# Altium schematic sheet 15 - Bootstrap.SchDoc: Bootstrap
size A3; PageSetup: Record=PageOptions¦CenterHorizontal=True¦CenterVertical=True¦PrintScale=0.70¦XCorrection=1.00¦YCorrection=1.00¦PrintKind=0¦BorderSize=5000000¦LeftOffset=0¦BottomOffset=0¦Orientation=2¦PaperLength=4200¦PaperWidth=2970¦Scale=100¦PaperSource=7¦PrintQuality=600¦MediaType=1¦DitherType=10¦PaperKind=A4¦PrintScaleMode=1; Author: Juan Anzola; SheetNumber: 15; SheetTotal: 20
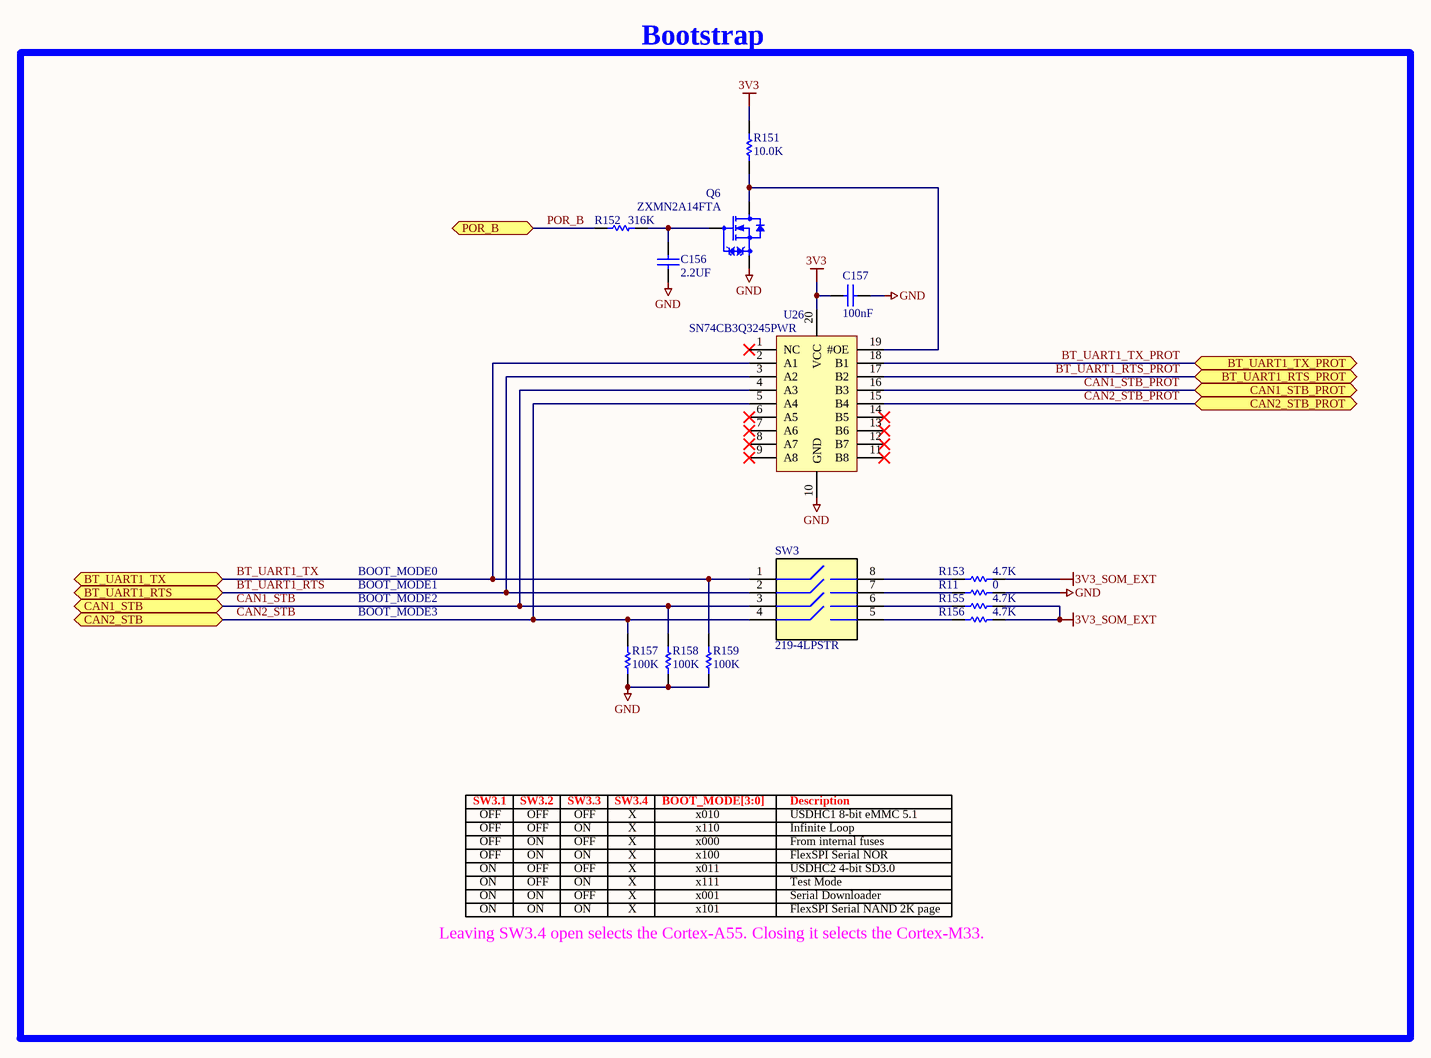
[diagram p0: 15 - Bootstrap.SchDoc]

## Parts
C156  2.2UF  [CAPC1608X90N]
C157  100nF  [CAPC1005X55N]
Q6  ZXMN2A14FTA  [SOT95P240X110_GSD-3N]
R11  0  [RESC1005X40N]
R151  10.0K  [RESC1005X40N]
R152  316K  [RESC1609X55N]
R153  4.7K  [RESC1005X40N]
R155  4.7K  [RESC1005X40N]
R156  4.7K  [RESC1005X40N]
R157  100K  [RESC1005X40N]
R158  100K  [RESC1005X40N]
R159  100K  [RESC1005X40N]
SW3  219-4LPSTR  [SOIC254P991X420-8N]
U26  SN74CB3Q3245PWR  [SOP65P640X120-20N]

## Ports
BT_UART1_RTS (bidir), BT_UART1_RTS_PROT (bidir), BT_UART1_TX (bidir), BT_UART1_TX_PROT (bidir), CAN1_STB (bidir), CAN1_STB_PROT (bidir), CAN2_STB (bidir), CAN2_STB_PROT (bidir), POR_B (bidir)

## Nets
3V3: C157.2 R151.2 U26.20(VCC)
3V3_SOM_EXT: R153.2 R155.2 R156.2
GND: C156.1 C157.1 Q6.S R11.2 R157.1 R158.1 R159.1 U26.10(GND)
BT_UART1_RTS: SW3.2 U26.3(A2) ; port BT_UART1_RTS
BT_UART1_RTS_PROT: U26.17(B2) ; port BT_UART1_RTS_PROT
BT_UART1_TX: R159.2 SW3.1 U26.2(A1) ; port BT_UART1_TX
BT_UART1_TX_PROT: U26.18(B1) ; port BT_UART1_TX_PROT
CAN1_STB: R158.2 SW3.3 U26.4(A3) ; port CAN1_STB
CAN1_STB_PROT: U26.16(B3) ; port CAN1_STB_PROT
CAN2_STB: R157.2 SW3.4 U26.5(A4) ; port CAN2_STB
CAN2_STB_PROT: U26.15(B4) ; port CAN2_STB_PROT
POR_B: R152.1 ; port POR_B
NetC156_2: C156.2 Q6.G R152.2
NetQ6_D: Q6.D R151.1 U26.19(#OE)
NetR11_1: R11.1 SW3.7
NetR153_1: R153.1 SW3.8
NetR155_1: R155.1 SW3.6
NetR156_1: R156.1 SW3.5

Not connected (* = marked no-connect by the designer): U26 1(NC)* 6(A5)* 7(A6)* 8(A7)* 9(A8)* 11(B8)* 12(B7)* 13(B6)* 14(B5)*

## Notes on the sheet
- Bootstrap
- BOOT_MODE0
- BOOT_MODE3
- BOOT_MODE2
- BOOT_MODE1
- SW3.1
- OFF
- SW3.2
- ON
- SW3.3
- SW3.4
- X
- BOOT_MODE[3:0]
- x010
- x000
- x110
- USDHC1 8-bit eMMC 5.1
- Infinite Loop
- From internal fuses
- Description
- x011
- x001
- x111
- x101
- x100
- FlexSPI Serial NOR
- Serial Downloader
- USDHC2 4-bit SD3.0
- FlexSPI Serial NAND 2K page
- Test Mode
- Leaving SW3.4 open selects the Cortex-A55. Closing it selects the Cortex-M33.

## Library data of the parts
C156 = 1001303: CAP CER 2.2UF 16V 10% X5R 0603; Part_Type: Capacitor; Manufacturer: TDK Corporation; Manufacturer_Part_Number: C1608X5R1C225K080AB; Digi_PN: 14050730; Component_Life_Cycle_State: Reviewed; Area: 2,27
C157 = 1000006: CAP 100nF 16V 10% X7R 0402; Part_Type: Capacitor; Manufacturer: Murata; Manufacturer_Part_Number: GRM155R71C104KA88D; Component_Life_Cycle_State: CAD Reviewed; Area: 0.95; Project: KITT; Tolerance: 10; Digi_PN: 14050552
Q6 = 1002855: MOSFET N-CH 20V 3.4A SOT23-3; Part_Type: Transistor; Manufacturer: Diodes, Inc.; Digi_PN: 17000304; Component_Life_Cycle_State: Pending
R11 = 1000076: RES 0.0 OHM 1/10W 0402 SMD; Part_Type: Resistor; Manufacturer: Panasonic - ECG; Manufacturer_Part_Number: ERJ-2GE0R00X; Digi_PN: 13050387; Component_Life_Cycle_State: Proven; Area: 0,95; Power_WV_SRF: 10
R151 = 1000537: RES 10.0K OHM 1/10W 1% 0402 SMD; Part_Type: Resistor; Manufacturer: Panasonic - ECG; Manufacturer_Part_Number: ERJ-2RKF1002X; Component_Life_Cycle_State: CAD Reviewed; Area: 0.95; Project: KITT; Power_WV_SRF: 100; Digi_PN: 13051084
R152 = 1001150: RES 316K OHM 1/10W 1% 0603 SMD; Part_Type: Resistor; Manufacturer: Yageo; Manufacturer_Part_Number: RC0603FR-07316KL; Digi_PN: 13050512; Component_Life_Cycle_State: Reviewed; Area: 1.5; Project: CCWMX6_SBC board; Power_WV_SRF: 100
R153 R155 R156 = 1000038: RES 4.7K OHM 1/10W 5% 0402 SMD; Part_Type: Resistor; Manufacturer: Panasonic - ECG; Manufacturer_Part_Number: ERJ-2GEJ472X; Digi_PN: 13050549; Component_Life_Cycle_State: Proven; Area: 0,95; Power_WV_SRF: 100; Tolerance: 5
R157-R159 = 1000480: RES 100K OHM 1/10W 1% 0402 SMD; Part_Type: Resistor; Manufacturer: Panasonic - ECG; Manufacturer_Part_Number: ERJ-2RKF1003X; Digi_PN: 13051063; Component_Life_Cycle_State: CAD Reviewed; Area: 0,95; Power_WV_SRF: 100
SW3 = 1002122: SWITCH SLIDE DIP SPST 100MA 20V; Manufacturer: CTS; Digi_PN: 22000318; Component_Life_Cycle_State: Created; Area: 155
U26 = 1001368: IC SWITCH BUS 8BIT FET 20-TSSOP; Manufacturer: Texas Instruments; Digi_PN: 16052042; Component_Life_Cycle_State: Reviewed; Area: 48,18; Project: ConnectCore i.MX6x SOM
